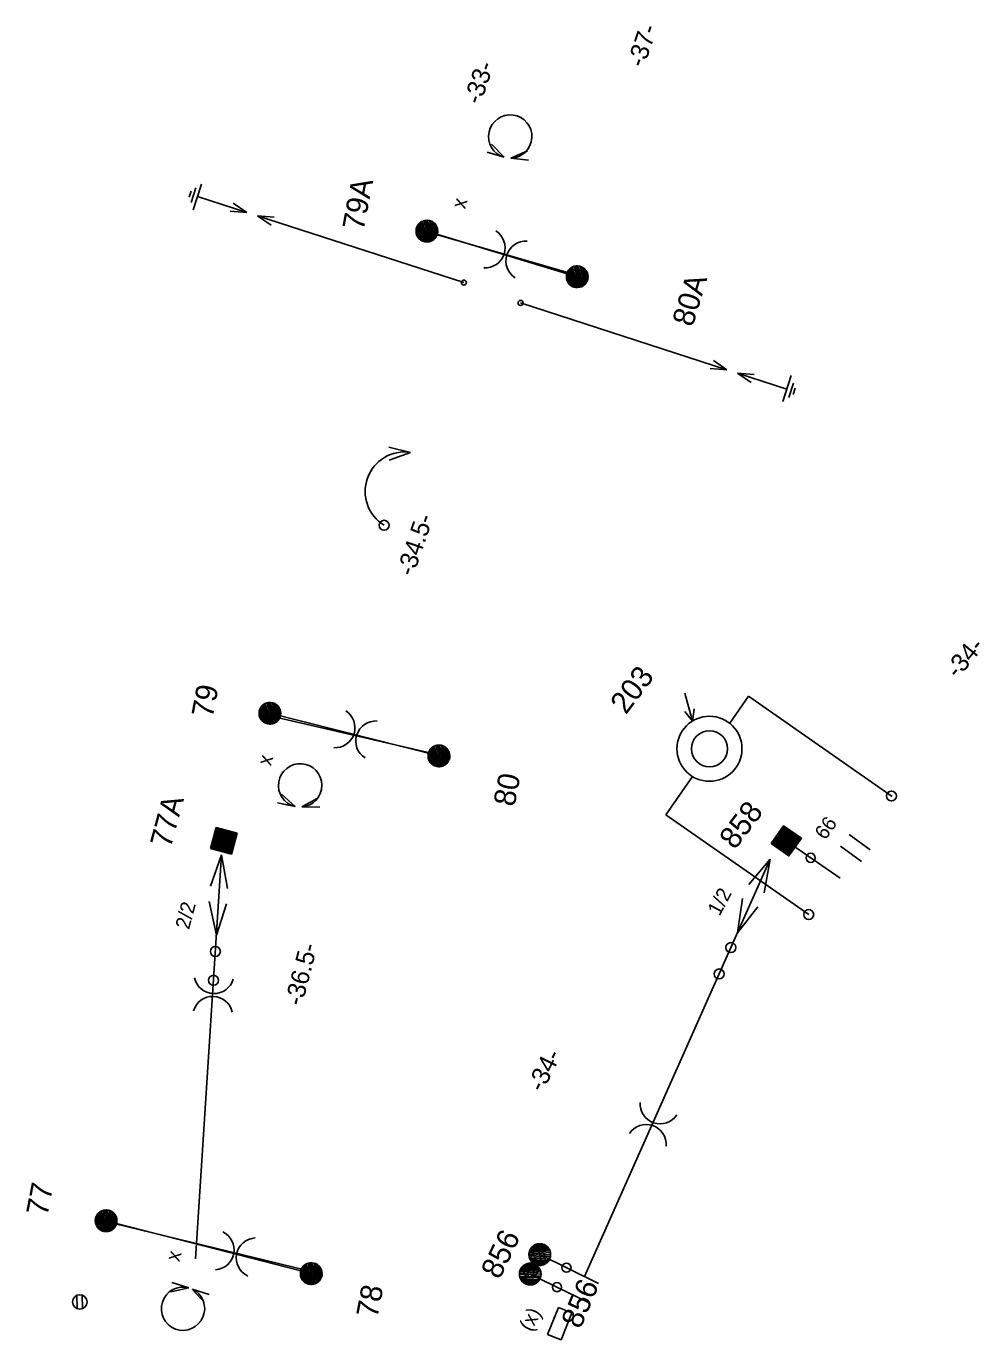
# Model space of a CAD drawing. Extents: x -595867 to -593796, y -1159595 to -1157495.
# Drawn here: x -594682.3 to -594616.4, y -1157775.9 to -1157685 of the extents above; entities that cross this region are included whole.
import ezdxf

# ---------------------------------------------------------------- set-up
doc = ezdxf.new("R2010")
doc.units = 0
for name, color, linetype in [('BVK_kanalizace_destova_nova', 7, 'Continuous'), ('BVK_kanalizace_jednotna_nova', 7, 'Continuous'), ('CD Telematika_novy', 7, 'Continuous')]:
    doc.layers.add(name, color=color, linetype=linetype)

# ---------------------------------------------------------------- blocks, each defined once
blk = doc.blocks.new('st_1t')
for points in [[(-0.00742, 0.00071), (0.00284, 0.0069), (0.00359, 0.00656), (-0.00747, -0.00023)], [(-0.00747, -0.00023), (0.00359, 0.00656), (0.00442, 0.00605), (-0.00743, -0.00101)], [(-0.00743, -0.00101), (0.00442, 0.00605), (0.00522, 0.0054), (-0.00722, -0.0019)], [(-0.00729, 0.00159), (0.00185, 0.00722), (0.00284, 0.0069), (-0.00742, 0.00071)], [(-0.00711, 0.00221), (0.00057, 0.00744), (0.00185, 0.00722), (-0.00729, 0.00159)], [(-0.00722, -0.0019), (0.00522, 0.0054), (0.00588, 0.00461), (-0.00688, -0.00302)], [(-0.00689, 0.00294), (-0.00011, 0.00749), (0.00057, 0.00744), (-0.00711, 0.00221)], [(-0.00669, 0.00331), (-0.00149, 0.00733), (-0.00011, 0.00749), (-0.00689, 0.00294)], [(-0.00688, -0.00302), (0.00588, 0.00461), (0.00666, 0.00341), (-0.00639, -0.00386)], [(-0.00627, 0.00403), (-0.00222, 0.00714), (-0.00149, 0.00733), (-0.00669, 0.00331)], [(-0.00639, -0.00386), (0.00666, 0.00341), (0.00712, 0.00224), (-0.00567, -0.00488)], [(-0.00579, 0.00472), (-0.00315, 0.00675), (-0.00222, 0.00714), (-0.00627, 0.00403)], [(-0.00526, 0.00533), (-0.00413, 0.00624), (-0.00315, 0.00675), (-0.00579, 0.00472)], [(-0.00567, -0.00488), (0.00712, 0.00224), (0.00742, 0.00112), (-0.00488, -0.00564)], [(-0.00488, -0.00564), (0.00742, 0.00112), (0.00748, -0.00042), (-0.00405, -0.00629)], [(-0.00405, -0.00629), (0.00748, -0.00042), (0.00729, -0.00175), (-0.00317, -0.00679)], [(-0.00317, -0.00679), (0.00729, -0.00175), (0.00698, -0.00275), (-0.00206, -0.00718)], [(-0.00206, -0.00718), (0.00698, -0.00275), (0.00651, -0.0037), (-0.00114, -0.0074)], [(-0.00114, -0.0074), (0.00651, -0.0037), (0.00592, -0.00458), (-0.00048, -0.00747)], [(-0.00048, -0.00747), (0.00592, -0.00458), (0.00536, -0.00524), (0.00037, -0.00747)], [(0.00037, -0.00747), (0.00536, -0.00524), (0.00449, -0.00597), (0.00138, -0.00739)], [(0.00138, -0.00739), (0.00449, -0.00597), (0.00384, -0.00644), (0.0025, -0.00702)], [(0.0025, -0.00702), (0.00384, -0.00644), (0.00295, -0.00692), (0.00293, -0.00693)]]:
    blk.add_lwpolyline(points, close=True)
blk.add_circle((0, 0), 0.0075)
blk = doc.blocks.new('st_bp')
for p, q in [((0.0075, 0.0075), (-0.0075, 0.0075)), ((-0.0075, 0.0075), (-0.0075, -0.0075)), ((-0.0075, -0.0075), (0.0075, 0.0075)), ((-0.0075, -0.00708), (0.00708, 0.0075)), ((-0.0075, -0.00665), (0.00665, 0.0075)), ((-0.0075, -0.00623), (0.00623, 0.0075)), ((-0.0075, -0.0058), (0.0058, 0.0075)), ((-0.0075, -0.00538), (0.00538, 0.0075)), ((-0.0075, -0.00495), (0.00495, 0.0075)), ((-0.0075, -0.00453), (0.00453, 0.0075)), ((-0.0075, -0.00411), (0.00411, 0.0075)), ((-0.0075, -0.00368), (0.00368, 0.0075)), ((-0.0075, -0.00326), (0.00326, 0.0075)), ((-0.0075, -0.00283), (0.00283, 0.0075)), ((-0.0075, -0.00241), (0.00241, 0.0075)), ((-0.0075, -0.00198), (0.00198, 0.0075)), ((-0.0075, -0.00156), (0.00156, 0.0075)), ((-0.0075, -0.00114), (0.00114, 0.0075)), ((-0.0075, -0.00071), (0.00071, 0.0075)), ((-0.0075, -0.00029), (0.00029, 0.0075)), ((-0.0075, 0.00014), (-0.00014, 0.0075)), ((-0.0075, 0.00056), (-0.00056, 0.0075)), ((-0.0075, 0.00099), (-0.00099, 0.0075)), ((-0.0075, 0.00141), (-0.00141, 0.0075)), ((-0.0075, 0.00183), (-0.00183, 0.0075)), ((-0.0075, 0.00226), (-0.00226, 0.0075)), ((-0.0075, 0.00268), (-0.00268, 0.0075)), ((-0.0075, 0.00311), (-0.00311, 0.0075)), ((-0.0075, 0.00353), (-0.00353, 0.0075)), ((-0.0075, 0.00396), (-0.00396, 0.0075)), ((-0.0075, 0.00438), (-0.00438, 0.0075)), ((-0.0075, 0.0048), (-0.0048, 0.0075)), ((-0.0075, 0.00523), (-0.00523, 0.0075)), ((-0.0075, 0.00565), (-0.00565, 0.0075)), ((-0.0075, 0.00608), (-0.00608, 0.0075)), ((-0.0075, 0.0065), (-0.0065, 0.0075)), ((-0.0075, 0.00692), (-0.00692, 0.0075)), ((-0.0075, 0.00735), (-0.00735, 0.0075)), ((-0.00708, -0.0075), (0.0075, 0.00708)), ((-0.00665, -0.0075), (0.0075, 0.00665)), ((-0.00623, -0.0075), (0.0075, 0.00623)), ((-0.0058, -0.0075), (0.0075, 0.0058)), ((-0.00538, -0.0075), (0.0075, 0.00538)), ((-0.00495, -0.0075), (0.0075, 0.00495)), ((-0.00453, -0.0075), (0.0075, 0.00453)), ((-0.00411, -0.0075), (0.0075, 0.00411)), ((-0.00368, -0.0075), (0.0075, 0.00368)), ((-0.00326, -0.0075), (0.0075, 0.00326)), ((-0.00283, -0.0075), (0.0075, 0.00283)), ((-0.00241, -0.0075), (0.0075, 0.00241)), ((-0.00198, -0.0075), (0.0075, 0.00198)), ((-0.00156, -0.0075), (0.0075, 0.00156)), ((-0.00114, -0.0075), (0.0075, 0.00114)), ((-0.00071, -0.0075), (0.0075, 0.00071)), ((-0.00029, -0.0075), (0.0075, 0.00029)), ((0.0075, -0.0075), (0.0075, 0.0075)), ((-0.0075, -0.0075), (0.0075, -0.0075)), ((0.00014, -0.0075), (0.0075, -0.00014)), ((0.00056, -0.0075), (0.0075, -0.00056)), ((0.00099, -0.0075), (0.0075, -0.00099)), ((0.00141, -0.0075), (0.0075, -0.00141)), ((0.00183, -0.0075), (0.0075, -0.00183)), ((0.00226, -0.0075), (0.0075, -0.00226)), ((0.00268, -0.0075), (0.0075, -0.00268)), ((0.00311, -0.0075), (0.0075, -0.00311)), ((0.00353, -0.0075), (0.0075, -0.00353)), ((0.00396, -0.0075), (0.0075, -0.00396)), ((0.00438, -0.0075), (0.0075, -0.00438)), ((0.0048, -0.0075), (0.0075, -0.0048)), ((0.00523, -0.0075), (0.0075, -0.00523)), ((0.00565, -0.0075), (0.0075, -0.00565)), ((0.00608, -0.0075), (0.0075, -0.00608)), ((0.0065, -0.0075), (0.0075, -0.0065)), ((0.00692, -0.0075), (0.0075, -0.00692)), ((0.00735, -0.0075), (0.0075, -0.00735))]:
    blk.add_line(p, q)
blk = doc.blocks.new('pol_izol')
for centre, start, end in [((-0.01484, 0), 284.40471, 75.59529), ((0.01484, 0), 104.40471, 255.59529)]:
    blk.add_arc(centre, 0.01384, start, end)
blk = doc.blocks.new('pol_sipka2')
for q in [(0.01228, 0.00302), (0.01182, -0.00341)]:
    blk.add_line((0, 0), q)
blk = doc.blocks.new('kotv_tecka')
blk.add_circle((0, 0), 0.00345)
blk = doc.blocks.new('pol_proptrnl')
for q in [(0.04362, 0.01209), (0.05182, 0.01539)]:
    blk.add_line((0.05362, 0), q)
blk.add_arc((0.02681, -0.00542), 0.02735, 11.42358, 168.57642)
blk.add_blockref('kotv_tecka', (0, 0))
blk = doc.blocks.new('st_2t')
for points in [[(-0.00779, 0.00818), (0.00247, 0.01437), (0.00322, 0.01403), (-0.00784, 0.00724)], [(-0.00784, 0.00724), (0.00322, 0.01403), (0.00405, 0.01352), (-0.0078, 0.00646)], [(-0.0078, 0.00646), (0.00405, 0.01352), (0.00485, 0.01287), (-0.00759, 0.00557)], [(-0.00767, 0.00906), (0.00148, 0.01469), (0.00247, 0.01437), (-0.00779, 0.00818)], [(-0.00748, 0.00968), (0.0002, 0.01491), (0.00148, 0.01469), (-0.00767, 0.00906)], [(-0.00759, 0.00557), (0.00485, 0.01287), (0.0055, 0.01208), (-0.00725, 0.00445)], [(-0.00727, 0.01041), (-0.00049, 0.01496), (0.0002, 0.01491), (-0.00748, 0.00968)], [(-0.00707, 0.01078), (-0.00187, 0.0148), (-0.00049, 0.01496), (-0.00727, 0.01041)], [(-0.00725, 0.00445), (0.0055, 0.01208), (0.00628, 0.01088), (-0.00676, 0.00361)], [(-0.00664, 0.0115), (-0.0026, 0.01461), (-0.00187, 0.0148), (-0.00707, 0.01078)], [(-0.00676, 0.00361), (0.00628, 0.01088), (0.00675, 0.00971), (-0.00604, 0.00259)], [(-0.00616, 0.01219), (-0.00352, 0.01422), (-0.0026, 0.01461), (-0.00664, 0.0115)], [(-0.00563, 0.0128), (-0.0045, 0.01371), (-0.00352, 0.01422), (-0.00616, 0.01219)], [(-0.00604, 0.00259), (0.00675, 0.00971), (0.00705, 0.00859), (-0.00525, 0.00183)], [(-0.00525, 0.00183), (0.00705, 0.00859), (0.00711, 0.00705), (-0.00442, 0.00118)], [(-0.00442, 0.00118), (0.00711, 0.00705), (0.00692, 0.00572), (-0.00354, 0.00068)], [(-0.00354, 0.00068), (0.00692, 0.00572), (0.00661, 0.00472), (-0.00243, 0.00029)], [(-0.00243, 0.00029), (0.00661, 0.00472), (0.00614, 0.00377), (-0.00151, 0.00007)], [(-0.00151, 0.00007), (0.00614, 0.00377), (0.00555, 0.00289), (-0.00086, 0)], [(-0.00086, 0), (0.00555, 0.00289), (0.00499, 0.00223), (0, 0)], [(0, 0), (0.00499, 0.00223), (0.00411, 0.0015), (0.001, 0.00008)], [(0.001, 0.00008), (0.00411, 0.0015), (0.00347, 0.00103), (0.00213, 0.00045)], [(0.00213, 0.00045), (0.00347, 0.00103), (0.00258, 0.00055), (0.00256, 0.00054)], [(-0.00779, -0.00682), (0.00247, -0.00063), (0.00322, -0.00097), (-0.00784, -0.00776)], [(-0.00784, -0.00776), (0.00322, -0.00097), (0.00405, -0.00148), (-0.0078, -0.00854)], [(-0.0078, -0.00854), (0.00405, -0.00148), (0.00485, -0.00213), (-0.00759, -0.00943)], [(-0.00767, -0.00594), (0.00148, -0.00031), (0.00247, -0.00063), (-0.00779, -0.00682)], [(-0.00748, -0.00532), (0.0002, -0.00009), (0.00148, -0.00031), (-0.00767, -0.00594)], [(-0.00759, -0.00943), (0.00485, -0.00213), (0.0055, -0.00292), (-0.00725, -0.01055)], [(-0.00727, -0.00459), (-0.00049, -0.00004), (0.0002, -0.00009), (-0.00748, -0.00532)], [(-0.00707, -0.00422), (-0.00187, -0.0002), (-0.00049, -0.00004), (-0.00727, -0.00459)], [(-0.00725, -0.01055), (0.0055, -0.00292), (0.00628, -0.00412), (-0.00676, -0.01139)], [(-0.00664, -0.0035), (-0.0026, -0.00039), (-0.00187, -0.0002), (-0.00707, -0.00422)], [(-0.00676, -0.01139), (0.00628, -0.00412), (0.00675, -0.00529), (-0.00604, -0.01241)], [(-0.00616, -0.00281), (-0.00352, -0.00078), (-0.0026, -0.00039), (-0.00664, -0.0035)], [(-0.00563, -0.0022), (-0.0045, -0.00129), (-0.00352, -0.00078), (-0.00616, -0.00281)], [(-0.00604, -0.01241), (0.00675, -0.00529), (0.00705, -0.00641), (-0.00525, -0.01317)], [(-0.00525, -0.01317), (0.00705, -0.00641), (0.00711, -0.00795), (-0.00442, -0.01382)], [(-0.00442, -0.01382), (0.00711, -0.00795), (0.00692, -0.00928), (-0.00354, -0.01432)], [(-0.00354, -0.01432), (0.00692, -0.00928), (0.00661, -0.01028), (-0.00243, -0.01471)], [(-0.00243, -0.01471), (0.00661, -0.01028), (0.00614, -0.01123), (-0.00151, -0.01493)], [(-0.00151, -0.01493), (0.00614, -0.01123), (0.00555, -0.01211), (-0.00086, -0.015)], [(-0.00086, -0.015), (0.00555, -0.01211), (0.00499, -0.01277), (0, -0.015)], [(0, -0.015), (0.00499, -0.01277), (0.00411, -0.0135), (0.001, -0.01492)], [(0.001, -0.01492), (0.00411, -0.0135), (0.00347, -0.01397), (0.00213, -0.01455)], [(0.00213, -0.01455), (0.00347, -0.01397), (0.00258, -0.01445), (0.00256, -0.01446)]]:
    blk.add_lwpolyline(points, close=True)
for centre in [(-0.00037, 0.00747), (-0.00037, -0.00753)]:
    blk.add_circle(centre, 0.0075)
blk = doc.blocks.new('st_tecka')
blk.add_circle((0, 0), 0.00314)
blk = doc.blocks.new('st2k_2t')
for p, q in [((-0.00037, 0.00747), (0.04494, 0.00747)), ((-0.00037, -0.00753), (0.04494, -0.00753))]:
    blk.add_line(p, q)
blk.add_blockref('st_2t', (0, 0))
at = {"rotation": 90}
for p in [(0.02017, 0.00747), (0.02017, -0.00753)]:
    blk.add_blockref('st_tecka', p, dxfattribs=at)
blk = doc.blocks.new('pol_sjsp')
for p, q in [((-0.01, 0.005), (0.01, 0.005)), ((-0.01, -0.005), (-0.01, 0.005)), ((0.01, 0.005), (0.01, -0.005)), ((0.01, -0.005), (-0.01, -0.005))]:
    blk.add_line(p, q)
blk = doc.blocks.new('kotv_poh')
for p, q in [((-0.05578, 0), (-0.03278, 0.00647)), ((-0.05578, 0), (-0.03363, -0.00562)), ((0, 0), (-0.02299, -0.00565))]:
    blk.add_line(p, q)
blk.add_lwpolyline([(0, 0), (-0.02214, 0.00639)])
for p in [(-0.08703, 0), (-0.06707, 0)]:
    blk.add_blockref('kotv_tecka', p)
blk = doc.blocks.new('blesk_zem')
for p, q in [((0.0104, 0.0777), (-0.0106, 0.0777)), ((0.0044, 0.0822), (-0.0046, 0.0822)), ((0.0179, 0.0717), (-0.0196, 0.0717)), ((0, 0), (0, 0.0717))]:
    blk.add_line(p, q)
blk = doc.blocks.new('blesk_ruzk')
for p, q in [((0, 0.3155), (-0.0055, 0.338)), ((0, 0.3155), (0.0063, 0.3372)), ((0, 0.3), (-0.0063, 0.2783)), ((0, 0), (0, 0.3)), ((0, 0.3), (0.0055, 0.2775))]:
    blk.add_line(p, q)
for name, p in [('blesk_zem', (0, 0.3155)), ('kotv_tecka', (0, 0))]:
    blk.add_blockref(name, p)
blk = doc.blocks.new('st1k_bp')
blk.add_line((0, 0), (0.04531, 0))
blk.add_blockref('st_bp', (0, 0))
at = {"rotation": 90}
blk.add_blockref('st_tecka', (0.02054, 0), dxfattribs=at)
blk = doc.blocks.new('pol_delic')
for p, q in [((-0.005, -0.00902), (-0.005, 0.00902)), ((0.005, -0.00902), (0.005, 0.00902))]:
    blk.add_line(p, q)
blk = doc.blocks.new('pol_sipk')
for q in [(0.0257, 0.0306), (0.0048, 0.0163), (0.0152, 0.0076)]:
    blk.add_line((0, 0), q)
blk = doc.blocks.new('odp_mzap')
for radius in [0.045, 0.025]:
    blk.add_circle((0, 0), radius)
blk.add_blockref('pol_sipk', (0.0179, 0.0413))

msp = doc.modelspace()

# ---------------------------------------------------------------- linework, layer by layer
at = {"layer": 'BVK_kanalizace_destova_nova'}
for p, q in [((-594654.61, -1157699.19), (-594644.22, -1157702.34)), ((-594633.669, -1157733.234), (-594632.365, -1157731.365)), ((-594632.365, -1157731.365), (-594622.446, -1157738.287)), ((-594665.47, -1157732.54), (-594653.78, -1157735.49)), ((-594638.087, -1157739.566), (-594636.239, -1157736.916)), ((-594628.207, -1157746.461), (-594638.087, -1157739.566)), ((-594643.724, -1157771.493), (-594630.865, -1157742.62)), ((-594676.8, -1157767.64), (-594662.61, -1157771.3))]:
    msp.add_line(p, q, dxfattribs=at)
for centre, start, end in [((-594648.848, -1157692.644), 271.34145, 253.52517), ((-594663.38, -1157737.526), 274.74043, 256.32202)]:
    msp.add_arc(centre, 1.5, start, end, dxfattribs=at)
at = {"layer": 'BVK_kanalizace_jednotna_nova'}
for p, q in [((-594654.723, -1157699.673), (-594654.883, -1157698.774)), ((-594654.353, -1157699.615), (-594654.515, -1157698.703)), ((-594644.333, -1157702.823), (-594644.493, -1157701.924)), ((-594643.963, -1157702.765), (-594644.125, -1157701.853)), ((-594665.561, -1157733.028), (-594665.762, -1157732.137)), ((-594665.194, -1157732.952), (-594665.397, -1157732.049)), ((-594653.871, -1157735.978), (-594654.072, -1157735.087)), ((-594653.504, -1157735.902), (-594653.707, -1157734.999)), ((-594668.032, -1157741.037), (-594669.285, -1157741.685)), ((-594668.534, -1157740.874), (-594669.128, -1157741.182)), ((-594630.123, -1157741.706), (-594630.239, -1157741.056)), ((-594629.689, -1157742.01), (-594629.936, -1157740.621)), ((-594629.385, -1157741.579), (-594629.502, -1157740.92)), ((-594668.193, -1157741.541), (-594668.78, -1157741.845)), ((-594676.977, -1157768.104), (-594677.014, -1157767.191)), ((-594676.602, -1157768.095), (-594676.64, -1157767.17)), ((-594647.038, -1157770.701), (-594647.236, -1157769.828)), ((-594646.667, -1157770.643), (-594646.876, -1157769.721)), ((-594662.787, -1157771.764), (-594662.824, -1157770.851)), ((-594662.412, -1157771.755), (-594662.45, -1157770.83)), ((-594647.576, -1157771.547), (-594647.773, -1157770.677)), ((-594647.205, -1157771.491), (-594647.413, -1157770.566)), ((-594678.797, -1157773.724), (-594678.834, -1157772.811)), ((-594678.422, -1157773.715), (-594678.46, -1157772.79))]:
    msp.add_line(p, q, dxfattribs=at)
for points in [[(-594644.642, -1157702.12), (-594654.209, -1157699.342)], [(-594654.319, -1157735.307), (-594664.888, -1157732.862)], [(-594668.334, -1157741.987), (-594669.287, -1157741.684), (-594668.985, -1157740.731), (-594668.032, -1157741.034), (-594668.334, -1157741.987)], [(-594630.506, -1157741.439), (-594629.934, -1157740.619), (-594629.114, -1157741.191), (-594629.686, -1157742.011), (-594630.506, -1157741.439)], [(-594662.995, -1157771.059), (-594676.234, -1157767.837)]]:
    msp.add_lwpolyline(points, dxfattribs=at)
for points in [[(-594668.334, -1157741.987), (-594669.287, -1157741.684), (-594668.985, -1157740.731), (-594668.032, -1157741.034)], [(-594630.506, -1157741.439), (-594629.934, -1157740.619), (-594629.114, -1157741.191), (-594629.686, -1157742.011)]]:
    msp.add_lwpolyline(points, close=True, dxfattribs=at)
for centre in [(-594654.61, -1157699.19), (-594654.61, -1157699.19), (-594644.22, -1157702.34), (-594644.22, -1157702.34), (-594665.47, -1157732.54), (-594665.47, -1157732.54), (-594653.78, -1157735.49), (-594653.78, -1157735.49), (-594676.8, -1157767.64), (-594676.8, -1157767.64), (-594646.923, -1157770.217), (-594646.923, -1157770.217), (-594662.61, -1157771.3), (-594662.61, -1157771.3), (-594647.457, -1157771.063), (-594647.457, -1157771.063), (-594678.62, -1157773.26), (-594678.62, -1157773.26)]:
    msp.add_circle(centre, 0.5, dxfattribs=at)
at = {"layer": 'CD Telematika_novy'}
msp.add_line((-594670.613, -1157770.277), (-594668.812, -1157742.324), dxfattribs=at)
msp.add_arc((-594671.484, -1157773.722), 1.5, 74.6123, 64.8214, dxfattribs=at)

# ---------------------------------------------------------------- block references
at = {"layer": 'BVK_kanalizace_destova_nova'}
for name, p, xscale, yscale, rotation in [('pol_sipka2', (-594649.273, -1157694.082), 100.00000000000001, -99.99999999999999, 147.32734801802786), ('pol_sipka2', (-594648.813, -1157694.143), 100, 100, 9.79136879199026), ('blesk_ruzk', (-594652.058, -1157702.75), 50.00000000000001, 49.99999999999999, 72.06723553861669), ('st_1t', (-594654.61, -1157699.19), 100.00000000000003, 99.99999999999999, 79.51685128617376), ('pol_izol', (-594649.172, -1157700.802), 100.00000000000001, 100, -17.932764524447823), ('st_1t', (-594644.22, -1157702.34), 100.00000000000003, 99.99999999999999, 79.51685128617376), ('blesk_ruzk', (-594648.135, -1157704.157), 49.99999999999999, 50, -107.93276446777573), ('pol_proptrnl', (-594657.575, -1157719.535), 100, 100, 70.09376142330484), ('odp_mzap', (-594635.071, -1157734.993), 50, 50, 55.09093375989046), ('st_1t', (-594665.47, -1157732.54), 100.00000000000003, 99.99999999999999, 79.51685128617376), ('pol_izol', (-594659.56, -1157733.997), 100, 100, -17.932764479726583), ('st_1t', (-594653.78, -1157735.49), 100.00000000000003, 99.99999999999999, 79.51685128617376), ('pol_sipka2', (-594663.734, -1157738.984), 100, -100, 151.91686583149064), ('kotv_tecka', (-594622.484, -1157738.26), 100, 100.00000000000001, 56.09093375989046), ('pol_sipka2', (-594663.256, -1157739.021), 100.00000000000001, 100, 15.464110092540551), ('st_bp', (-594668.66, -1157741.36), 100.00000000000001, 99.99999999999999, -15.357243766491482), ('st1k_bp', (-594629.76, -1157741.367), 100, 100, -34.73137939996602), ('pol_delic', (-594624.983, -1157741.867), 100, 100, 53.95994915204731), ('kotv_poh', (-594668.812, -1157742.324), 100.00000000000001, 99.99999999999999, 86.31302570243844), ('kotv_poh', (-594630.865, -1157742.62), 100, 100, 65.99346204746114), ('kotv_tecka', (-594628.207, -1157746.461), 100, 100.00000000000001, 56.09093375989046), ('pol_izol', (-594638.963, -1157760.961), 100, 100, 71.23269516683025), ('st_1t', (-594676.8, -1157767.64), 100.00000000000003, 99.99999999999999, 79.51685128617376), ('pol_izol', (-594667.871, -1157769.932), 100.00000000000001, 99.99999999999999, -10.844079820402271), ('st2k_2t', (-594647.101, -1157770.668), 100, 100.00000000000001, -26.137652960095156), ('st_1t', (-594662.61, -1157771.3), 100.00000000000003, 99.99999999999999, 79.51685128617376), ('pol_sjsp', (-594645.428, -1157774.757), 99.99999999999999, 100.00000000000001, 68.34177072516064)]:
    msp.add_blockref(name, p, dxfattribs=dict(at, xscale=xscale, yscale=yscale, rotation=rotation))
at = {"layer": 'CD Telematika_novy'}
for name, p, xscale, yscale, rotation in [('pol_izol', (-594669.382, -1157752.024), 100, 99.99999999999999, 88.1479301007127), ('pol_sipka2', (-594671.086, -1157772.276), 100.00000000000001, 100, 178.772085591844), ('pol_sipka2', (-594670.846, -1157772.365), 99.99999999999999, -100, -34.19682333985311)]:
    msp.add_blockref(name, p, dxfattribs=dict(at, xscale=xscale, yscale=yscale, rotation=rotation))

# ---------------------------------------------------------------- texts
at = {"layer": 'BVK_kanalizace_destova_nova'}
for s, height, rotation, p in [('-37-', 1.25, 71.18409, (-594639.616, -1157687.94)), ('-33-', 1.25, 71.18409, (-594650.915, -1157690.499)), ('79A', 1.5, 79.02055, (-594659.003, -1157699.201)), ('x', 1, 74.94815, (-594651.968, -1157697.705)), ('80A', 1.5, 73.25922, (-594636.241, -1157705.867)), ('-34.5-', 1.25, 71.18409, (-594655.559, -1157723.125)), ('-34-', 1.25, 50.44544, (-594617.907, -1157730.207)), ('203', 1.5, 53.00891, (-594640.849, -1157732.679)), ('79', 1.5, 79.02055, (-594669.438, -1157732.91)), ('x', 1, 74.94815, (-594665.4, -1157736.22)), ('80', 1.5, 79.02055, (-594648.558, -1157739.049)), ('77A', 1.5, 74.94815, (-594672.334, -1157741.907)), ('858', 1.5, 53.00891, (-594633.309, -1157742.029)), ('66', 1, 54.27581, (-594627.062, -1157741.358)), ('1/2', 1, 61.84245, (-594634.377, -1157746.611)), ('2/2', 1, 74.94815, (-594671.069, -1157747.54)), ('-36.5-', 1.25, 75.58226, (-594663.253, -1157752.839)), ('-34-', 1.25, 63.41509, (-594646.616, -1157758.812)), ('77', 1.5, 79.02055, (-594680.869, -1157767.369)), ('856', 1.5, 63.86616, (-594649.599, -1157771.758)), ('x', 1, 74.94815, (-594671.743, -1157770.516)), ('78', 1.5, 79.02055, (-594658.043, -1157774.428)), ('(x)', 1, 61.84245, (-594647.409, -1157775.367))]:
    msp.add_text(s, height=height, rotation=rotation, dxfattribs=at).set_placement(p)
at = {"layer": 'BVK_kanalizace_jednotna_nova'}
msp.add_text('856', height=1.5, rotation=67.01, dxfattribs=at).set_placement((-594644.003, -1157775.183))

doc.saveas('drawing.dxf')
